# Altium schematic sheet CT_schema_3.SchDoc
size 215 x 229 mm
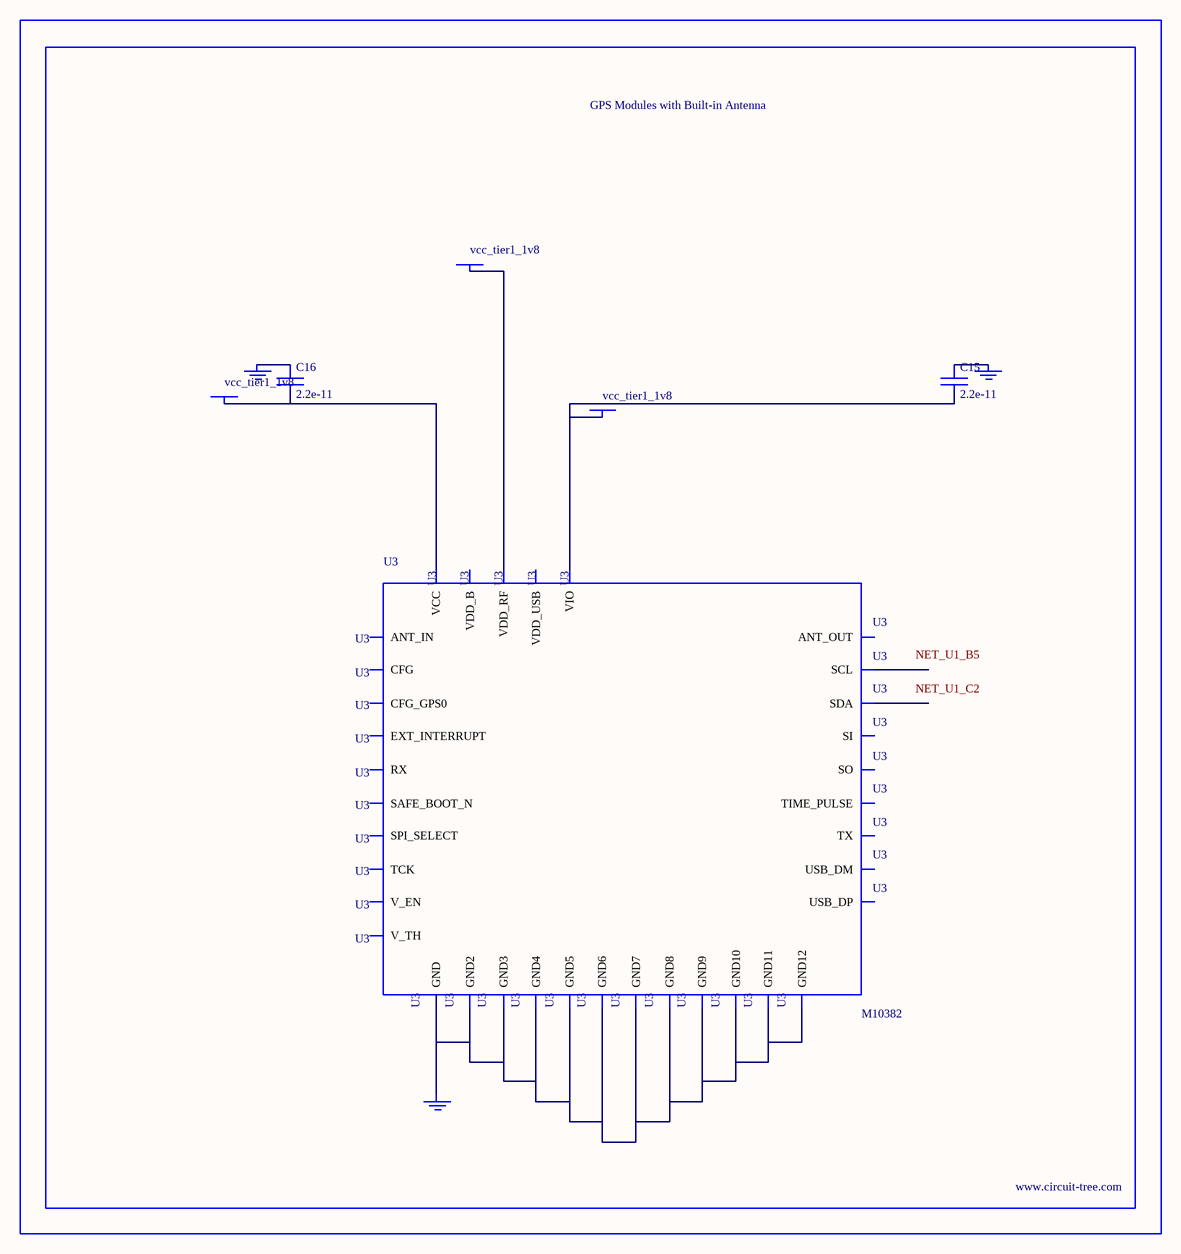
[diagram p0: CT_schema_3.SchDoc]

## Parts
BORDER2  (no value)
C15  2.2e-11  [C0402]
C16  2.2e-11  [C0402]
GND_INSTANCE_2_0  (no value)
GND_INSTANCE_2_1  (no value)
GND_INSTANCE_2_2  (no value)
POWER_INSTANCE_2_0  vcc_tier1_1v8
POWER_INSTANCE_2_1  vcc_tier1_1v8
POWER_INSTANCE_2_2  vcc_tier1_1v8
U3  M10382  [M10382]

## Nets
NetC15_1: C15.1 GND_INSTANCE_2_0.0(GND)
NetC15_2: C15.2 POWER_INSTANCE_2_0.0(PWR) U3.5(VIO)
NetC16_1: C16.1 GND_INSTANCE_2_1.0(GND)
NetC16_2: C16.2 POWER_INSTANCE_2_2.0(PWR) U3.27(VCC)
NetGND_INSTANCE_2_2_0: GND_INSTANCE_2_2.0(GND) U3.2(GND) U3.4(GND2) U3.14(GND3) U3.17(GND4) U3.21(GND5) U3.24(GND6) U3.26(GND7) U3.28(GND8) U3.33(GND9) U3.34(GND10) U3.35(GND11) U3.36(GND12)
NetPOWER_INSTANCE_2_1_0: POWER_INSTANCE_2_1.0(PWR) U3.25(VDD_RF)

Not connected (* = marked no-connect by the designer): U3 1(ANT_IN) 3(ANT_OUT) 6(USB_DP) 7(USB_DM) 8(SO) 9(CFG_GPS0) 10(SPI_SELECT) 11(TX) 12(V_TH) 13(RX) 15(VDD_B) 16(SI) 18(SDA) 19(SCL) 20(SAFE_BOOT_N) 22(TCK) 23(TIME_PULSE) 29(EXT_INTERRUPT) 30(V_EN) 31(CFG) 32(VDD_USB)

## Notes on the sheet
- Labels drawn without touching a wire or pin: NET_U1_B5, NET_U1_C2

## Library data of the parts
BORDER2 = BORDER_PAGE2
C15 C16 = C0402C220K3RAC
GND_INSTANCE_2_0-GND_INSTANCE_2_2 = GND
POWER_INSTANCE_2_0-POWER_INSTANCE_2_2 = PWR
